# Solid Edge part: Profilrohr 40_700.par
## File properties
Username: ahadarics
Dokumentum tartalom típus: 0
Author: ahadarics
Last saved by: ahadarics
Revision: 94
Sűrűség: 0,000 kg/m^3
Pontosság: 0,990
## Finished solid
Body 1: solid body, 175 faces, 519 edges, 346 vertices.
  Faces by surface: cylinder 107, plane 68
  Edges by curve: line 305, circle 214
Bounding box of the edges (mm): 51.354 x 51.354 x 743.000, from (-25.6768, -25.6768, -709) to (25.6768, 25.6768, 34).
Cylindrical faces by radius (mm): R0.1 x16, R0.2 x30, R0.5 x28, R1 x8, R2.7 x8, R3.5 x4, R5 x4, R20 x1, R22 x8
Planar faces by outward normal: +x 6, +y 6, +z 1, -x 4, -y 4, -z 1, oblique 46
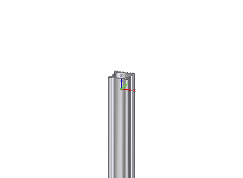
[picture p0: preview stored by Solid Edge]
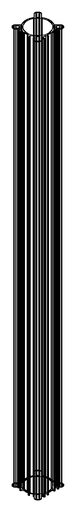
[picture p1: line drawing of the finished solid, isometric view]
